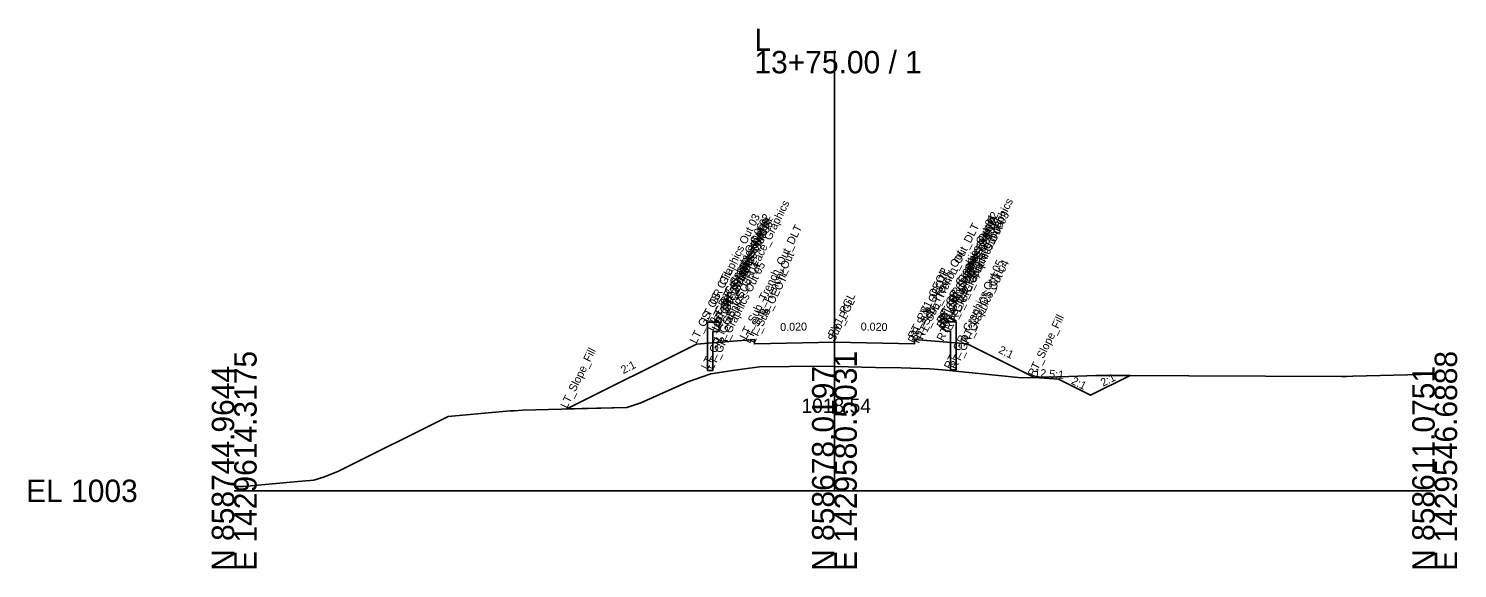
# Model space of a CAD drawing. Extents: x -26 to 176, y -10 to 13058.
# Drawn here: x -25.7 to 152.8, y 4490.3 to 4557.8 of the extents above; entities that cross this region are included whole.
import ezdxf

# ---------------------------------------------------------------- set-up
doc = ezdxf.new("R2010")
doc.units = 0
for name, color, linetype in [('Default', 7, 'Continuous'), ('Exist Cross Section Cell', 7, 'Continuous'), ('Exist XS Center Line Elevation Label', 7, 'Continuous'), ('Exist XS Ground Line', 7, 'Continuous'), ('Old_Level_50', 7, 'Continuous'), ('Prop CMT Guardrail Graphics', 7, 'Continuous'), ('Prop CMT Pvmt Course 1', 7, 'Continuous'), ('Prop CMT Pvmt Surface Shoulder', 7, 'Continuous'), ('Prop CMT Shld Paved Course 1', 7, 'Continuous'), ('Prop CMT Slope Grass', 7, 'Continuous'), ('Prop CMT Subgrade Earthwork', 7, 'Continuous'), ('Prop XS Dump Level', 7, 'Continuous'), ('Prop XS SE Text', 7, 'Continuous'), ('Prop XS Side Slope Text', 7, 'Continuous')]:
    doc.layers.add(name, color=color, linetype=linetype)

msp = doc.modelspace()

# ---------------------------------------------------------------- linework, layer by layer
at = {"layer": 'Exist Cross Section Cell'}
for p, q in [((75, 4500), (75, 4554.97)), ((0, 4500), (75, 4500)), ((75, 4500), (150, 4500))]:
    msp.add_line(p, q, dxfattribs=at)
at = {"layer": 'Exist XS Ground Line'}
msp.add_lwpolyline([(0, 4500.56), (1.18, 4500.54), (7.93, 4501.16), (9.97, 4501.35), (11.27, 4501.76), (13.05, 4502.45), (26.75, 4509.29), (34.47, 4509.98), (34.98, 4510.01), (36.03, 4510.1), (49.06, 4510.42), (50.82, 4510.99), (56.7, 4513.61), (59.56, 4514.62), (62.54, 4515.08), (65.64, 4515.49), (69.39, 4515.54), (73.72, 4515.57), (75, 4515.54), (80.14, 4515.43), (83.32, 4515.38), (86.93, 4515.25), (88.52, 4515.14), (98.36, 4514.13), (104.28, 4514.3), (107.65, 4514.43), (109.74, 4514.43), (138.38, 4514.29), (139, 4514.3), (139.79, 4514.33), (150, 4514.57)], dxfattribs=at)
at = {"layer": 'Old_Level_50'}
for points in [[(88.52, 4515.14), (98.36, 4514.13), (99.98, 4514.18), (91.59, 4518.37), (88.59, 4518.61), (85, 4518.9), (85, 4518.36), (75, 4518.56), (65, 4518.36), (65, 4518.9), (60.75, 4518.56), (57.75, 4518.32), (41.58, 4510.23), (49.06, 4510.42), (50.82, 4510.99), (56.7, 4513.61), (59.56, 4514.62), (62.54, 4515.08), (65.64, 4515.49), (69.39, 4515.54), (73.72, 4515.57), (75, 4515.54), (80.14, 4515.43), (83.32, 4515.38), (86.93, 4515.25)], [(62.54, 4515.08), (65.64, 4515.49), (69.39, 4515.54), (73.72, 4515.57), (75, 4515.54), (80.14, 4515.43), (83.32, 4515.38), (86.93, 4515.25), (88.52, 4515.14), (98.36, 4514.13), (99.98, 4514.18), (91.59, 4518.37), (88.59, 4518.61), (85, 4518.9), (85, 4518.36), (75, 4518.56), (65, 4518.36), (65, 4518.9), (60.75, 4518.56), (57.75, 4518.32), (41.58, 4510.23), (49.06, 4510.42), (50.82, 4510.99), (56.7, 4513.61), (59.56, 4514.62)], [(62.54, 4515.08), (65.64, 4515.49), (69.39, 4515.54), (73.72, 4515.57), (75, 4515.54), (80.14, 4515.43), (83.32, 4515.38), (86.93, 4515.25), (88.52, 4515.14), (98.36, 4514.13), (99.98, 4514.18), (91.59, 4518.37), (88.59, 4518.61), (85, 4518.9), (85, 4518.36), (75, 4518.56), (65, 4518.36), (65, 4518.9), (60.75, 4518.56), (57.75, 4518.32), (41.58, 4510.23), (49.06, 4510.42), (50.82, 4510.99), (56.7, 4513.61), (59.56, 4514.62)], [(99.98, 4514.18), (104.28, 4514.3), (107.65, 4514.43), (109.74, 4514.43), (111.93, 4514.42), (106.98, 4511.94), (102.98, 4513.94)], [(99.98, 4514.18), (102.98, 4513.94), (106.98, 4511.94), (111.93, 4514.42), (109.74, 4514.43), (107.65, 4514.43), (104.28, 4514.3)], [(99.98, 4514.18), (102.98, 4513.94), (106.98, 4511.94), (111.93, 4514.42), (109.74, 4514.43), (107.65, 4514.43), (104.28, 4514.3)]]:
    msp.add_lwpolyline(points, close=True, dxfattribs=at)
at = {"layer": 'Prop CMT Guardrail Graphics'}
for points in [[(59.15, 4515.06), (59.15, 4521.06)], [(59.15, 4521.06), (60.48, 4521.06), (60.75, 4520.77)], [(60.75, 4520.77), (60.48, 4520.48)], [(60.48, 4520.48), (60.75, 4520.19)], [(90.19, 4521.11), (88.86, 4521.11), (88.59, 4520.82)], [(88.59, 4520.82), (88.86, 4520.53)], [(88.86, 4520.53), (88.59, 4520.24)], [(90.19, 4515.11), (90.19, 4521.11)], [(60.75, 4520.19), (60.48, 4519.9), (59.82, 4519.9)], [(59.82, 4519.9), (59.82, 4515.06)], [(88.59, 4520.24), (88.86, 4519.95), (89.52, 4519.95)], [(89.52, 4519.95), (89.52, 4515.11)], [(89.52, 4515.11), (90.19, 4515.11)], [(59.82, 4515.06), (59.15, 4515.06)]]:
    msp.add_lwpolyline(points, dxfattribs=at)
at = {"layer": 'Prop CMT Pvmt Course 1'}
for points in [[(65, 4518.9), (65, 4518.36)], [(85, 4518.9), (85, 4518.36)], [(65, 4518.36), (75, 4518.56)], [(85, 4518.36), (75, 4518.56)]]:
    msp.add_lwpolyline(points, dxfattribs=at)
at = {"layer": 'Prop CMT Pvmt Surface Shoulder'}
for points in [[(65, 4518.9), (65, 4518.9)], [(85, 4518.9), (85, 4518.9)]]:
    msp.add_lwpolyline(points, dxfattribs=at)
at = {"layer": 'Prop CMT Shld Paved Course 1'}
for points in [[(65, 4518.9), (65, 4518.9)], [(65, 4518.36), (65, 4518.9)], [(85, 4518.9), (85, 4518.9)], [(85, 4518.36), (85, 4518.9)]]:
    msp.add_lwpolyline(points, dxfattribs=at)
at = {"layer": 'Prop CMT Slope Grass'}
for p, q in [((99.98, 4514.18), (102.98, 4513.94)), ((106.98, 4511.94), (102.98, 4513.94)), ((106.98, 4511.94), (111.93, 4514.42))]:
    msp.add_line(p, q, dxfattribs=at)
for points in [[(65, 4518.9), (60.75, 4518.56)], [(85, 4518.9), (88.59, 4518.61)], [(85, 4518.9), (91.59, 4518.37), (99.98, 4514.18)], [(57.75, 4518.32), (41.58, 4510.23)], [(60.75, 4518.56), (57.75, 4518.32)], [(88.59, 4518.61), (91.59, 4518.37)], [(91.59, 4518.37), (99.98, 4514.18)]]:
    msp.add_lwpolyline(points, dxfattribs=at)
at = {"layer": 'Prop CMT Subgrade Earthwork'}
for points in [[(75, 4518.56), (65, 4518.36)], [(75, 4518.56), (85, 4518.36)]]:
    msp.add_lwpolyline(points, dxfattribs=at)

# ---------------------------------------------------------------- texts
at = {"layer": 'Default'}
msp.add_text('-', height=0.0001, dxfattribs=at).set_placement((0, 4500))
at = {"layer": 'Exist Cross Section Cell'}
for s, p in [('L', (65, 4554.97)), ('13+75.00 / 1', (65, 4552.17)), ('EL 1003', (-26, 4498.6))]:
    msp.add_text(s, height=2.8, dxfattribs=at).set_placement(p)
for s, p in [('E 1429614.3175', (2.8, 4490)), ('E 1429580.5031', (77.8, 4490)), ('E 1429546.6888', (152.8, 4490)), ('N 858744.9644', (0, 4490)), ('N 858678.0197', (75, 4490)), ('N 858611.0751', (150, 4490))]:
    msp.add_text(s, height=2.8, rotation=90, dxfattribs=at).set_placement(p)
at = {"layer": 'Exist XS Center Line Elevation Label'}
msp.add_text('1018.54', height=1.8, dxfattribs=at).set_placement((70.87, 4509.74))
msp.add_text('1018.54', height=1.8, dxfattribs=at).set_placement((70.87, 4509.74))
msp.add_text('1018.54', height=1.8, dxfattribs=at).set_placement((70.87, 4509.74))
at = {"layer": 'Prop XS Dump Level'}
for s, p in [('LT_GS_OS_GR_Face_Graphics', (60.75, 4518.56)), ('RT_GS_OS_GR_Face_Graphics', (88.59, 4518.61)), ('RT_GR_Graphics Out 02', (88.86, 4521.11)), ('RT_GR_Graphics Out 03', (90.19, 4521.11)), ('LT_GR_Graphics Out 03', (59.15, 4521.06)), ('LT_GR_Graphics Out 06', (59.82, 4519.9)), ('LT_GR_Graphics Out 02', (60.48, 4521.06)), ('LT_GR_Graphics Out 09', (60.48, 4520.48)), ('LT_GR_Graphics Out 07', (60.48, 4519.9)), ('LT_GR_Graphics Out 01', (60.75, 4520.77)), ('LT_GR_Graphics Out 08', (60.75, 4520.19)), ('LT_Sub_Trench_Out_DLT', (63.98, 4518.82)), ('RT_Sub_Trench_Out_DLT', (86.02, 4518.82)), ('RT_GR_Graphics Out 01', (88.59, 4520.82)), ('RT_GR_Graphics Out 08', (88.59, 4520.24)), ('RT_GR_Graphics Out 09', (88.86, 4520.53)), ('RT_GR_Graphics Out 07', (88.86, 4519.95)), ('RT_GR_Graphics Out 06', (89.52, 4519.95)), ('LT_Sub_Trench_Out', (64.45, 4518.35)), ('RT_Sub_Trench_Out', (85.55, 4518.35)), ('LT_GR_Graphics Out 04', (59.15, 4515.06)), ('LT_GR_Graphics Out 05', (59.82, 4515.06)), ('LT_PV1_OEOT', (65, 4518.9)), ('LT_PS1_OEOP', (65, 4518.9)), ('RT_PV1_OEOT', (85, 4518.9)), ('RT_PS1_OEOP', (85, 4518.9)), ('RT_GR_Graphics Out 05', (89.52, 4515.11)), ('RT_GR_Graphics Out 04', (90.19, 4515.11)), ('RT_GS_OS_CTL', (91.59, 4518.37)), ('LT_GS_OS_CTL', (57.75, 4518.32)), ('LT_GS_OS_CTL', (57.75, 4518.32)), ('LT_Sub_OEOT', (65, 4518.36)), ('RT_Sub_OEOT', (85, 4518.36)), ('PV1_PGL', (75, 4519.1)), ('Sub_PGL', (75, 4518.56)), ('RT_Slope_Fill', (99.98, 4514.18)), ('RT_Slope_Fill', (99.98, 4514.18)), ('LT_Slope_Fill', (41.58, 4510.23))]:
    msp.add_text(s, height=1, rotation=63.5833, dxfattribs=at).set_placement(p)
at = {"layer": 'Prop XS SE Text'}
for rotation, p in [(1.1458, (68.23, 4519.97)), (358.8542, (78.27, 4520.04))]:
    msp.add_text('0.020', height=1, rotation=rotation, dxfattribs=at).set_placement(p)
at = {"layer": 'Prop XS Side Slope Text'}
for s, rotation, p in [('2:1', 333.4349, (95.41, 4517.3)), ('2:1', 26.565, (48.62, 4514.59)), ('12.5:1', 355.4261, (99.94, 4514.29)), ('2:1', 333.4349, (104.5, 4513.42)), ('2:1', 26.5651, (108.56, 4513))]:
    msp.add_text(s, height=1, rotation=rotation, dxfattribs=at).set_placement(p)

doc.saveas('drawing.dxf')
